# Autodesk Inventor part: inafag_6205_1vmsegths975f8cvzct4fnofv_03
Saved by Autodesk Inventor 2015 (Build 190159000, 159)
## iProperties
Company: TraceParts S.A.
Created: 2012-12
Part Number: inafag_6205_1vmsegths975f8cvzct4fnofv_03
Checked By: TraceParts S.A.
Catalog Web Link: www.traceparts.com
Document SubType Name: Modeling
Designer: TraceParts
Material: Generic
Density: 1 g/cm^3
Appearance: Default
Author: TraceParts
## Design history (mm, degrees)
feature "inafag_6205_1vmsegths975f8cvzct4fnofv"
body "Solid1"
